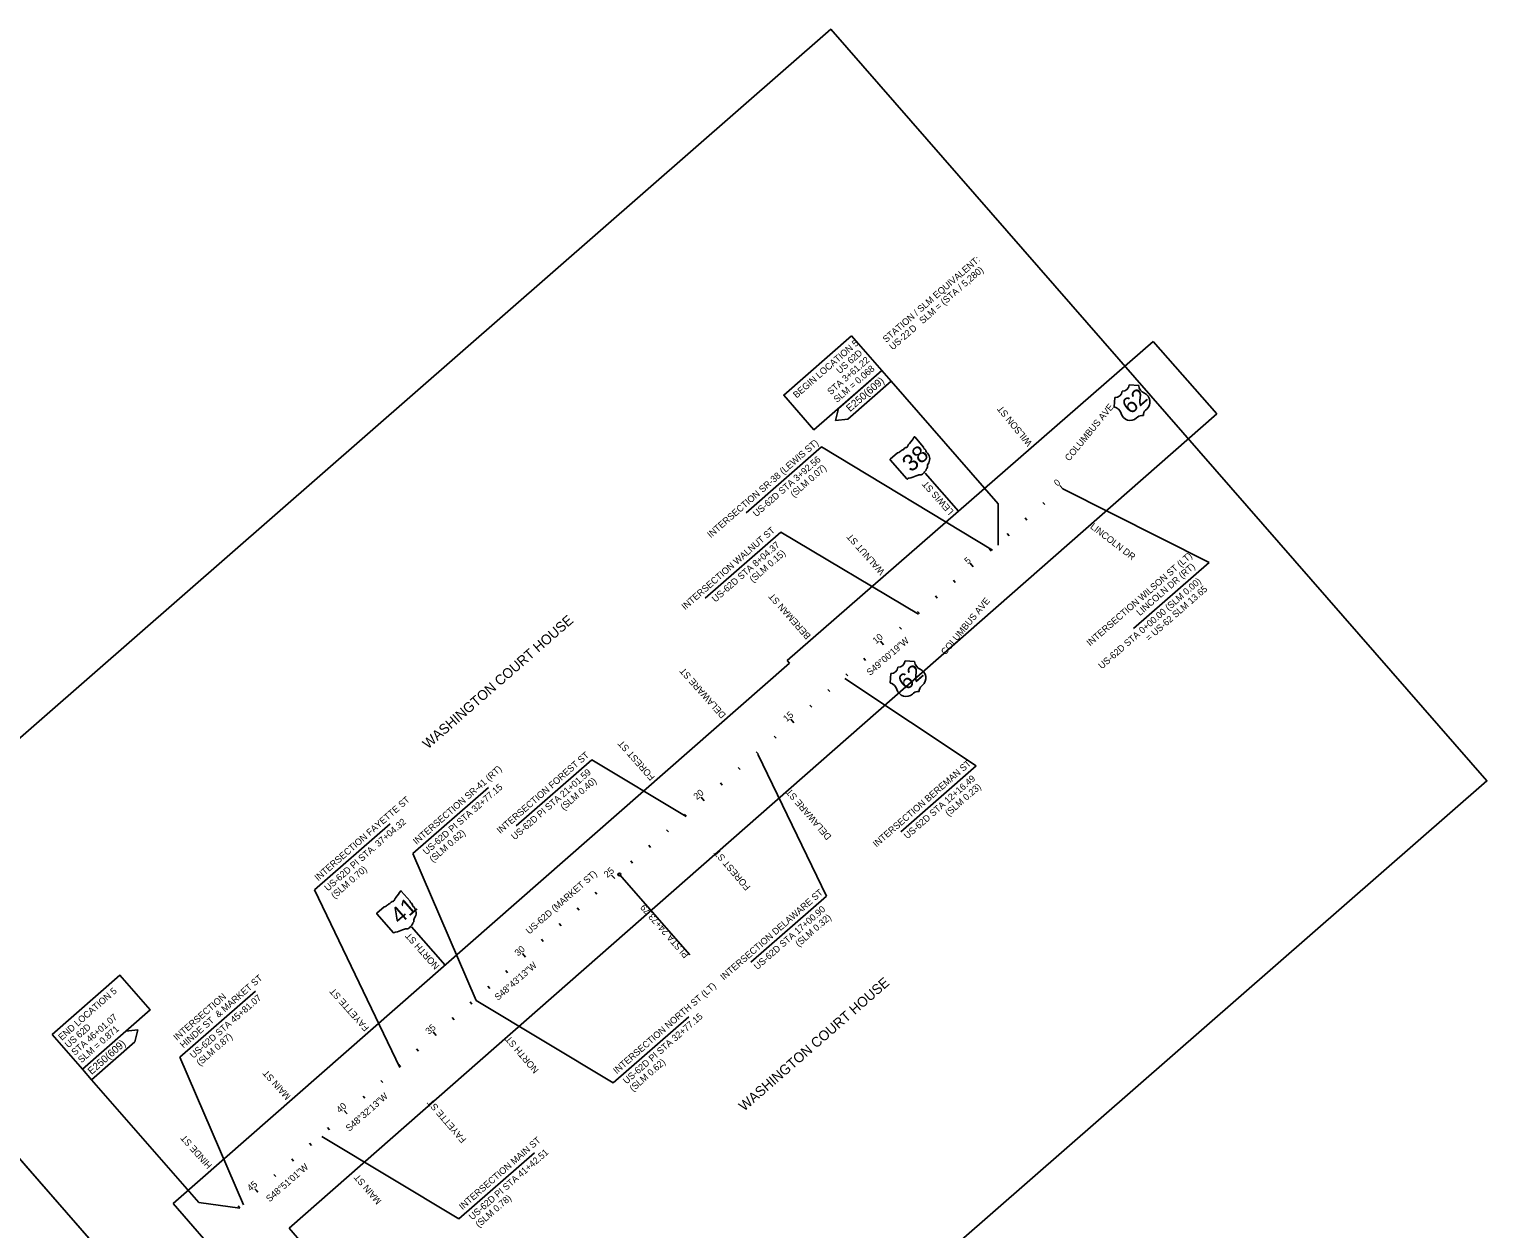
# Model space of a CAD drawing. Extents: x 127199 to 143299, y 479188 to 491521.
# Drawn here: x 137161 to 143299, y 486473 to 491521 of the extents above; entities that cross this region are included whole.
import ezdxf

# ---------------------------------------------------------------- set-up
doc = ezdxf.new("R2010")
doc.units = 0
for name, color, linetype in [('PM_P_Parking_Lot_Stall', 7, 'Continuous'), ('PM_P_Stop_Line', 7, 'Continuous'), ('PM_X_CL_Double_Solid', 7, 'Continuous'), ('PM_X_Crosswalk', 7, 'Continuous'), ('PM_X_Lane_Line', 7, 'Continuous'), ('PV_X_Parking_Lot', 7, 'Continuous'), ('PV_X_Walk', 7, 'Continuous'), ('RD_X_RR_2', 7, 'Continuous')]:
    doc.layers.add(name, color=color, linetype=linetype)

msp = doc.modelspace()

# ---------------------------------------------------------------- linework, layer by layer
at = {"layer": 'PM_P_Parking_Lot_Stall'}
for p, q in [((141074.9, 489492.8), (140934.5, 489652.7)), ((138912.3, 487582.2), (138771, 487743.2))]:
    msp.add_line(p, q, dxfattribs=at)
at = {"layer": 'PM_P_Stop_Line'}
for p, q in [((140927.3, 489762.8), (140890.6, 489805)), ((140818.3, 489738.5), (140787.2, 489711.4)), ((140927.3, 489762.8), (140927.3, 489762.8)), ((140787.3, 489709.1), (140857.5, 489628.5)), ((138764.8, 487852.1), (138728.1, 487894.3)), ((138655.8, 487827.8), (138624.7, 487800.7)), ((138764.8, 487852.1), (138764.8, 487852.1)), ((138624.8, 487798.4), (138695, 487717.8))]:
    msp.add_line(p, q, dxfattribs=at)
for centre, radius, start, end in [((140890.3, 489757.9), 30, 138.39607, 161.81874), ((140758.8, 489879.9), 149.3, 316.89436, 329.95634), ((140889.3, 489804.1), 1.57, 32.91197, 138.78789), ((140817.5, 489754.3), 15.8, 272.66939, 312.16177), ((140869.1, 489703.1), 56.8, 121.53658, 136.03816), ((140840.1, 489756), 4.57, 260.84195, 338.15226), ((140853.2, 489751.1), 9.49, 95.51657, 160.19102), ((140851.3, 489771.9), 11.4, 274.90609, 335.87808), ((140926.2, 489761.5), 1.68, 330.6537, 48.78402), ((140929.7, 489759.5), 2.43, 148.99387, 251.38685), ((140922.7, 489744), 14.6, 21.08285, 64.69945), ((140946.9, 489748.8), 10.6, 177.85639, 227.97948), ((140915.8, 489712.3), 37.4, 333.35877, 50.03573), ((140788.4, 489710.3), 1.63, 139.17999, 229.17999), ((140911.7, 489666.8), 21.4, 271.75026, 327.34172), ((140945.3, 489647), 17.6, 126.74501, 152.25984), ((140927.5, 489669.9), 11.4, 309.82691, 356.59916), ((140942, 489668.8), 3.21, 106.80162, 173.69831), ((140931.4, 489679), 12.1, 323.92308, 4.327), ((140963.8, 489681.2), 20.5, 135.45301, 183.62664), ((140858.9, 489629.4), 1.65, 213.00827, 299.3565), ((140851.9, 489637.8), 12.6, 308.38888, 321.65374), ((140864.9, 489626.8), 4.53, 70.79827, 134.32164), ((140845, 489736.7), 107.8, 281.46281, 298.24839), ((140911.3, 489611.6), 33.7, 88.23404, 116.88586), ((138596.3, 487969.3), 149.3, 316.89436, 329.95634), ((138726.8, 487893.5), 1.57, 32.91197, 138.78789), ((138655, 487843.6), 15.8, 272.66939, 312.16177), ((138706.5, 487792.5), 56.8, 121.53658, 136.03816), ((138677.6, 487845.4), 4.57, 260.84195, 338.15226), ((138690.7, 487840.5), 9.49, 95.51657, 160.19102), ((138688.8, 487861.3), 11.4, 274.90609, 335.87808), ((138727.8, 487847.3), 30, 138.39607, 161.81874), ((138763.7, 487850.9), 1.68, 330.6537, 48.78402), ((138767.2, 487848.8), 2.43, 148.99387, 251.38685), ((138760.2, 487833.3), 14.6, 21.08285, 64.69945), ((138784.4, 487838.2), 10.6, 177.85639, 227.97948), ((138753.3, 487801.7), 37.4, 333.35877, 50.03573), ((138625.9, 487799.7), 1.63, 139.17999, 229.17999), ((138782.8, 487736.4), 17.6, 126.74501, 152.25984), ((138764.9, 487759.2), 11.4, 309.82691, 356.59916), ((138779.5, 487758.2), 3.21, 106.80162, 173.69831), ((138768.8, 487768.4), 12.1, 323.92308, 4.327), ((138801.3, 487770.6), 20.5, 135.45301, 183.62664), ((138696.4, 487718.7), 1.65, 213.00827, 299.3565), ((138689.4, 487727.1), 12.6, 308.38888, 321.65374), ((138702.4, 487716.1), 4.53, 70.79827, 134.32164), ((138682.5, 487826.1), 107.8, 281.46281, 298.24839), ((138748.8, 487701), 33.7, 88.23404, 116.88586), ((138749.2, 487756.1), 21.4, 271.75026, 327.34172)]:
    msp.add_arc(centre, radius, start, end, dxfattribs=at)
at = {"layer": 'PM_X_CL_Double_Solid'}
msp.add_line((139646.5, 487963.6), (139943.4, 487625.4), dxfattribs=at)
msp.add_circle((139646.5, 487963.6), 6, dxfattribs=at)
at = {"layer": 'PM_X_Crosswalk'}
for p, q in [((141833.3, 490021.2), (141793.2, 490024)), ((141733.3, 489971.6), (141730.6, 489931.5)), ((141862.6, 489918.5), (141866.9, 489922.3)), ((141824.1, 489884.9), (141828.4, 489888.6)), ((140889.4, 488859.6), (140849.3, 488862.3)), ((140789.4, 488810), (140786.7, 488769.9)), ((140918.7, 488756.9), (140923, 488760.6)), ((140880.2, 488723.2), (140884.5, 488727))]:
    msp.add_line(p, q, dxfattribs=at)
for centre, radius, start, end in [((141764.9, 490026.2), 28.4, 266.70395, 355.55796), ((141872.9, 490025.5), 39.8, 186.13003, 246.58383), ((141734.9, 490000), 28.4, 266.70395, 355.55796), ((141841.1, 489952.5), 39.8, 310.49269, 66.29904), ((141721, 489892.9), 39.8, 15.67808, 76.13189), ((141797.6, 489914.6), 39.8, 195.96288, 311.76922), ((141881.3, 489897.1), 28.4, 131.13096, 184.26106), ((141847.1, 489867.2), 28.4, 78.00086, 131.13096), ((140821, 488864.5), 28.4, 266.70395, 355.55796), ((140929, 488863.8), 39.8, 186.13003, 246.58383), ((140791, 488838.3), 28.4, 266.70395, 355.55796), ((140897.2, 488790.9), 39.8, 310.49269, 66.29904), ((140777.1, 488731.2), 39.8, 15.67808, 76.13189), ((140853.7, 488752.9), 39.8, 195.96288, 311.76922), ((140903.2, 488705.6), 28.4, 78.00086, 131.13096), ((140937.4, 488735.5), 28.4, 131.13096, 184.26106)]:
    msp.add_arc(centre, radius, start, end, dxfattribs=at)
at = {"layer": 'PM_X_Lane_Line'}
for p, q in [((140568.6, 489925.2), (140751.1, 490084.6)), ((140751.1, 490084.6), (140790.3, 490039.8)), ((140790.3, 490039.8), (140607.8, 489880.4)), ((140790.3, 490039.8), (141240.9, 489523.7)), ((140556.2, 489874.8), (140568.6, 489925.2)), ((140607.8, 489880.4), (140556.2, 489874.8)), ((140498.2, 489763.9), (140179.9, 489485.9)), ((141217.4, 489328.8), (140498.2, 489763.9)), ((141513.7, 489586.4), (142129.5, 489277.2)), ((141241, 489349.4), (141240.9, 489523.7)), ((140326.5, 489405.1), (140008.2, 489127.2)), ((140906.5, 489058.7), (140326.5, 489405.1)), ((142129.5, 489277.2), (141811.3, 488999.3)), ((140595.5, 488788.4), (141149.5, 488421.4)), ((139530, 488446.9), (139211.7, 488168.9)), ((139927.4, 488207.7), (139530, 488446.9)), ((140229.9, 488470.6), (140518.9, 487872.2)), ((141149.5, 488421.4), (140831.3, 488143.4)), ((138777.2, 488052.1), (139095.5, 488330.1)), ((138362.9, 487899.1), (138681.2, 488177)), ((139042.8, 487433.6), (138777.2, 488052.1)), ((138721.8, 487151.8), (138362.9, 487899.1)), ((140518.9, 487872.2), (140200.6, 487594.2)), ((137796, 487195.3), (138114.3, 487473.2)), ((139042.8, 487433.6), (139620, 487087.1)), ((139620, 487087.1), (139938.3, 487365.1)), ((137567.5, 487304.3), (137385, 487144.9)), ((137424.2, 487100.1), (137606.7, 487259.5)), ((137619.1, 487309.9), (137567.5, 487304.3)), ((137606.7, 487259.5), (137619.1, 487309.9)), ((137385, 487144.9), (137424.2, 487100.1)), ((138063.2, 486573), (137796, 487195.3)), ((137424.2, 487100.1), (137875.4, 486583.4)), ((138393.4, 486861.6), (138970.6, 486515.2)), ((138970.6, 486515.2), (139288.9, 486793.1)), ((138048.1, 486559.9), (137875.4, 486583.4))]:
    msp.add_line(p, q, dxfattribs=at)
for points in [[(140623.9, 490230.3), (140338.4, 489981), (140465.7, 489835.3), (140751.1, 490084.6)], [(137257.7, 487290.6), (137543.2, 487539.9), (137670.5, 487394.2), (137385, 487144.9)]]:
    msp.add_lwpolyline(points, close=True, dxfattribs=at)
at = {"layer": 'PV_X_Walk'}
for p, q in [((141513.7, 489586.4), (141500.5, 489601.5)), ((141438.2, 489520.8), (141430.3, 489529.8)), ((141362.7, 489455.2), (141354.8, 489464.2)), ((141287.2, 489389.6), (141279.4, 489398.6)), ((141211.8, 489324), (141203.9, 489333)), ((141136.3, 489258.4), (141123.2, 489273.5)), ((141060.8, 489192.8), (141052.9, 489201.8)), ((140985.3, 489127.2), (140977.5, 489136.2)), ((140909.8, 489061.6), (140902, 489070.6)), ((140834.4, 488996), (140826.5, 489005)), ((140758.9, 488930.4), (140745.8, 488945.5)), ((140683.4, 488864.8), (140675.5, 488873.8)), ((140607.9, 488799.2), (140600.1, 488808.2)), ((140532.5, 488733.6), (140524.6, 488742.6)), ((140457, 488668), (140449.1, 488677)), ((140381.5, 488602.4), (140368.4, 488617.5)), ((140306, 488536.8), (140298.2, 488545.8)), ((140230.6, 488471.2), (140222.7, 488480.2)), ((140155.1, 488405.6), (140147.2, 488414.6)), ((140079.6, 488340), (140071.7, 488349)), ((140004.1, 488274.4), (139991, 488289.5)), ((139928.6, 488208.8), (139920.8, 488217.8)), ((139853.2, 488143.2), (139845.3, 488152.2)), ((139777.7, 488077.6), (139769.8, 488086.6)), ((139702.2, 488012), (139694.3, 488021)), ((139626.8, 487946.3), (139613.6, 487961.3)), ((139551.7, 487880.3), (139543.8, 487889.3)), ((139476.5, 487814.3), (139468.6, 487823.4)), ((139401.4, 487748.4), (139393.5, 487757.4)), ((139326.2, 487682.4), (139318.3, 487691.4)), ((139251.1, 487616.4), (139237.9, 487631.4)), ((139175.9, 487550.4), (139168, 487559.5)), ((139100.8, 487484.5), (139092.9, 487493.5)), ((139025.6, 487418.5), (139017.7, 487427.5)), ((138950.5, 487352.5), (138942.6, 487361.5)), ((138875.3, 487286.6), (138862.1, 487301.6)), ((138800.2, 487220.6), (138792.3, 487229.6)), ((138725, 487154.6), (138717.1, 487163.6)), ((138650.1, 487088.4), (138642.1, 487097.4)), ((138575.1, 487022.2), (138567.2, 487031.2)), ((138500.2, 486956), (138487, 486971)), ((138500.2, 486956), (138492.3, 486965)), ((138425.3, 486889.8), (138417.3, 486898.8)), ((138350.1, 486823.8), (138342.2, 486832.8)), ((138274.8, 486758), (138266.9, 486767)), ((138199.5, 486692.2), (138191.6, 486701.2)), ((138124.2, 486626.4), (138111.1, 486641.4)), ((138124.2, 486626.4), (138116.3, 486635.4)), ((138048.9, 486560.6), (138041, 486569.6))]:
    msp.add_line(p, q, dxfattribs=at)
at = {"layer": 'RD_X_RR_2'}
for p, q in [((140353.3, 488864.6), (141894.5, 490206.5)), ((141894.5, 490206.5), (142161.7, 489901.9)), ((142161.7, 489901.9), (138255.8, 486474.9)), ((140363.2, 488853.2), (140353.3, 488864.6)), ((137766.9, 486578.7), (140363.2, 488853.2)), ((136629.2, 487330.1), (139006.1, 484608.4)), ((137987.5, 486326.2), (137766.9, 486578.7)), ((138255.8, 486474.9), (138634.2, 486040.3))]:
    msp.add_line(p, q, dxfattribs=at)
msp.add_lwpolyline([(136243.4, 487771.9), (140536.7, 491521.2), (143299.3, 488357.8), (139006.1, 484608.4)], close=True, dxfattribs=at)

# ---------------------------------------------------------------- texts
at = {"layer": 'PM_P_Stop_Line'}
for s, p in [('38', (140875.3, 489654)), ('41', (138721.1, 487750.6))]:
    msp.add_text(s, height=70.41, rotation=41.04989, dxfattribs=at).set_placement(p)
at = {"layer": 'PM_X_CL_Double_Solid'}
for s, p in [('24+73.79', (139856.7, 487723.5)), (' STA. ', (139919.1, 487652.5)), ('PI', (139941.4, 487627))]:
    msp.add_text(s, height=28, rotation=131.2798, dxfattribs=at).set_placement(p)
at = {"layer": 'PM_X_Crosswalk'}
for p in [(141799.6, 489897.4), (140855.7, 488735.8)]:
    msp.add_text('62', height=68.22, rotation=41.13096, dxfattribs=at).set_placement(p)
at = {"layer": 'PM_X_Lane_Line'}
for s, height, rotation, p in [('STATION / SLM EQUIVALENT:', 28, 41.13096, (140770.3, 490200.6)), ('SLM = (STA / 5,280)', 28, 41.13096, (140924.2, 490279.3)), ('D ', 28, 41.13096, (140881.4, 490241.9)), ('BEGIN LOCATION 5', 28, 41.00101, (140392.6, 489966.7)), ('US-22', 28, 41.13096, (140797.9, 490169)), ('US 62', 28, 41.00101, (140574.3, 490069.1)), ('D', 28, 41.00101, (140652, 490136.6)), ('STA 3+61.22', 28, 41.00101, (140536.6, 489980.6)), ('SLM = 0.068', 28, 41.00101, (140563, 489947.9)), ('E250(609)', 31.2, 41.00101, (140617.7, 489909.2)), ('WILSON ST', 28, 129.20417, (141386.7, 489780.2)), ('COLUMBUS AVE', 28, 50.49793, (141540.9, 489701.1)), ('INTERSECTION SR-38 (LEWIS ST)', 28, 41.13096, (140031.3, 489378.5)), ('US-62D STA 3+92.56', 28, 41.13096, (140223.3, 489467.2)), ('(SLM 0.07)', 28, 41.13096, (140381.1, 489549.2)), ('LEWIS ST', 28, 131.62353, (141056.1, 489492.6)), ('INTERSECTION WALNUT ST', 28, 41.13096, (139923.3, 489075.5)), ('LINCOLN DR', 28, 322.42042, (141626.5, 489423)), ('US-62D STA 8+04.37', 28, 41.13096, (140050.8, 489107.7)), ('WALNUT ST', 28, 131.62353, (140765.8, 489239.9)), ('(SLM 0.15)', 28, 41.13096, (140209.4, 489190.4)), ('INTERSECTION WILSON ST (LT)', 28, 41.13096, (141628.6, 488923.2)), ('LINCOLN DR (RT)', 28, 41.13096, (141838.4, 489050.7)), ('US-62D STA 0+00.00 (SLM 0.00)', 28, 41.13096, (141678.2, 488826.5)), ('= US-62 SLM 13.65', 28, 41.13096, (141876.8, 488944.1)), ('BEREMAN ST', 28, 131.62353, (140454.6, 488968.9)), ('COLUMBUS AVE', 28, 50.37628, (141019.3, 488885.3)), ('WASHINGTON COURT HOUSE', 42, 41.13096, (138840.3, 488489.9)), ('DELAWARE ST', 28, 131.62353, (140097, 488636.2)), ('FOREST ST', 28, 131.62353, (139798.3, 488374.5)), ('INTERSECTION FOREST ST', 28, 41.13096, (139145.4, 488133.5)), ('INTERSECTION BEREMAN ST', 28, 41.13096, (140729, 488076.6)), ('INTERSECTION SR-41 (RT)', 28, 41.13096, (138792.4, 488087.9)), ('US-62D PI STA 21+01.59', 28, 41.13096, (139205.9, 488107.2)), ('(SLM 0.40)', 28, 41.13096, (139412.9, 488232.2)), ('US-62D STA 12+16.49', 28, 41.13096, (140858.9, 488111)), ('US-62D PI STA 32+77.15', 28, 41.13096, (138833.7, 488044.8)), ('DELAWARE ST', 28, 130.63839, (140541.3, 488124.1)), ('(SLM 0.23)', 28, 41.13096, (141032.9, 488207.1)), ('INTERSECTION FAYETTE ST', 28, 41.13096, (138378.1, 487934.8)), ('US-62D PI STA. 37+04.32', 28, 41.13096, (138419.3, 487891.7)), ('(SLM 0.62)', 28, 41.13096, (138861.3, 488013.2)), ('FOREST ST', 28, 130.63839, (140200.3, 487911.6)), ('(SLM 0.70)', 28, 41.13096, (138447, 487860.1)), ('US-62D (MARKET ST)', 28, 41.2798, (139267.3, 487710.5)), ('INTERSECTION DELAWARE ST', 28, 41.13096, (140086.5, 487517)), ('US-62D STA 17+00.90', 28, 41.13096, (140227.4, 487561)), ('(SLM 0.32)', 28, 41.13096, (140401.8, 487657.5)), ('NORTH ST', 28, 131.62353, (138890.5, 487579.2)), ('HINDE ST  & MARKET ST', 28, 41.13096, (137811.2, 487231)), ('INTERSECTION NORTH ST (LT)', 28, 41.13096, (139635.2, 487122.9)), ('WASHINGTON COURT HOUSE', 42, 41.13096, (140171.9, 486965.2)), ('END LOCATION 5', 28, 41.26091, (137298.5, 487263.6)), ('INTERSECTION ', 28, 41.13096, (137783.6, 487262.6)), ('US-62D STA 45+81.07', 28, 41.13096, (137852.5, 487187.9)), ('FAYETTE ST', 28, 131.62353, (138595, 487319.3)), ('US-62D PI STA 32+77.15', 28, 41.13096, (139676.4, 487079.8)), ('STA 46+01.07', 28, 41.26091, (137353.9, 487200.5)), ('SLM = 0.871', 28, 41.26091, (137381.6, 487168.9)), ('D', 28, 41.26091, (137403.6, 487299.9)), ('US 62', 28, 41.26091, (137326.2, 487232.1)), ('E250(609)', 31.2, 41.26091, (137424, 487119.5)), ('(SLM 0.87)', 28, 41.13096, (137880.1, 487156.3)), ('NORTH ST', 28, 130.63839, (139309.3, 487141.9)), ('MAIN ST', 28, 131.62353, (138264.2, 487030.5)), ('(SLM 0.62)', 28, 41.13096, (139704, 487048.2)), ('FAYETTE ST', 28, 130.63839, (139003.5, 486848.8)), ('HINDE ST', 28, 131.62353, (137933.2, 486740.5)), ('INTERSECTION MAIN ST', 28, 41.13096, (138985.8, 486550.9)), ('US-62D PI STA 41+42.51', 28, 41.13096, (139027, 486507.8)), ('MAIN ST', 28, 130.63839, (138646.7, 486590.3)), ('(SLM 0.78)', 28, 41.13096, (139054.7, 486476.2))]:
    msp.add_text(s, height=height, rotation=rotation, dxfattribs=at).set_placement(p)
at = {"layer": 'PV_X_Parking_Lot'}
for s, rotation, p in [('S49°00\'19"W', 40.99475, (140702.2, 488799.1)), ('S48°43\'13"W', 41.2798, (139135.6, 487431.9)), ('S48°32\'13"W', 41.46318, (138509.3, 486880.7)), ('S48°51\'01"W', 41.14971, (138173.3, 486583.7))]:
    msp.add_text(s, height=28, rotation=rotation, dxfattribs=at).set_placement(p)
at = {"layer": 'PV_X_Walk'}
for s, rotation, p in [('0', 40.99475, (141491, 489595.7)), ('5', 40.99475, (141113.9, 489267.9)), ('10', 40.99475, (140727.8, 488932.3)), ('15', 40.99475, (140350.7, 488604.6)), ('20', 40.99475, (139973, 488276.4)), ('25', 41.2798, (139596.1, 487948.5)), ('30', 41.2798, (139220.1, 487618.3)), ('35', 41.2798, (138844.6, 487288.7)), ('40', 41.46318, (138469.3, 486957.8)), ('45', 41.14971, (138093.5, 486628.6))]:
    msp.add_text(s, height=28, rotation=rotation, dxfattribs=at).set_placement(p)

doc.saveas('drawing.dxf')
